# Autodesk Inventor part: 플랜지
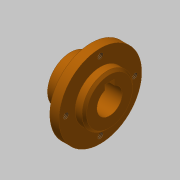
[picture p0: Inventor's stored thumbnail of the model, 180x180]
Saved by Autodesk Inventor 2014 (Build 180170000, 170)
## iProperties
Created: 2019-10
Part Number: 플랜지
Material: 스테인리스강
Document SubType Name: Modeling
Designer: mduedu
Density: 1 g/cm^3
Appearance: 주황색
Author: mduedu
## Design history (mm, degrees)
sketch "스케치1"
  geometry: L1 (0, 0)-(9, 0); L2 (9, 0)-(9, 10); L3 (9, 10)-(0, 10); L4 (0, 10)-(0, 0); L5 (9, 0)-(13, 0); L6 (13, 0)-(13, 18); L7 (13, 18)-(9, 18); L8 (9, 18)-(9, 0); L9 (13, 0)-(17, 0); L10 (17, 0)-(17, 11); L11 (17, 11)-(13, 11); L12 (13, 11)-(13, 0)
  constraints: 24 end point, 6 parallel, 3 horizontal, 3 perpendicular
  dimensions: "d0" = 17 distance between parallel lines of L10 L4; "d2" = 20 diameter of L3 L1; "d3" = 22 diameter of L11 L9; "d4" = 36 diameter of L7 L5; "d5" = 4 distance of L6.end L7.end; "d6" = 4 distance of L10.end L11.end
revolve "회전1" sketch "스케치1" stored, may be unused: angle "d7" = 90 deg
sketch "스케치2"
  geometry: L1 (-2, 5.123)-(2, 5.123); L2 (2, 5.123)-(2, 7.3); L3 (2, 7.3)-(-2, 7.3); L4 (-2, 7.3)-(-2, 5.123); A1 r 5.5 centre (0, 0) between (-2, 5.123) and (2, 5.123); 1 further point
  constraints: 8 end point, 2 parallel, 2 point on circle, 1 centre point, 1 coincident, 1 horizontal, 1 perpendicular
  dimensions: "d8" = 11 diameter of A1; "d10" = 4 distance of L2.end L3.end; "d11" = 7.3 distance from line of L3 point (0, 0)
extrude "돌출1" cut sketch "스케치2" stored distance "d12" = 10; taper "d13" = 0 deg
chamfer "모따기1" distance "d14" = 1; stored, may be unused: second distance "d15" = 2, angle "d16" = 45 deg
chamfer "모따기2" distance "d17" = 1; stored, may be unused: second distance "d18" = 2, angle "d19" = 45 deg
sketch "스케치3" dims "d20" = 30
  geometry: 3 further points
  constraints: 2 vertical alignment, 1 coincident, 2 other
hole "구멍1" sketch "스케치3" at (0, 15) diameter "d21" = 2.459; stored, may be unused: countersink angle "d25" = 90 deg, drill point angle "d27" = 118 deg; dims "d22" = 6, "d23" = 4, "d24" = 2, "d26" = 8
node "솔리드1"
pattern_circular "원형 패턴1" dims angle "d29" = 360 deg
